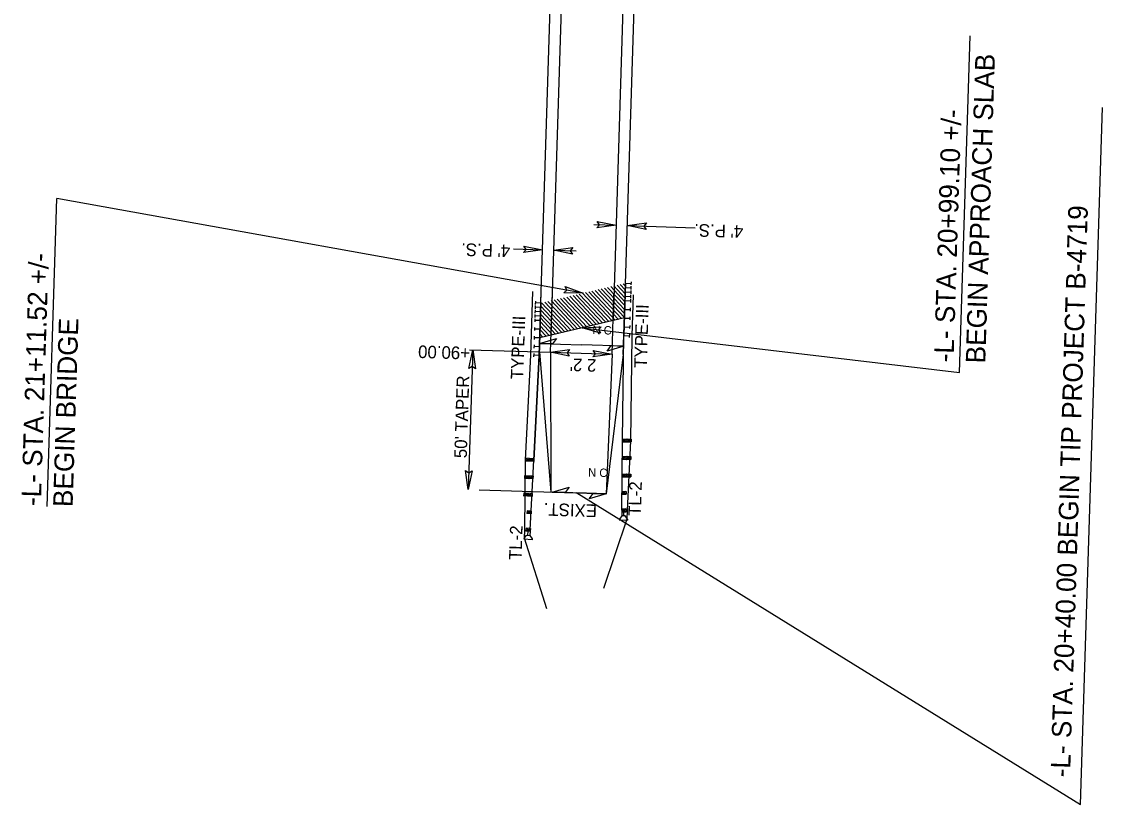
# Model space of a CAD drawing. Extents: x 1515198 to 1515601, y 565062 to 565830.
# Drawn here: x 1515197.9 to 1515584.6, y 565062 to 565342 of the extents above; entities that cross this region are included whole.
import ezdxf

# ---------------------------------------------------------------- set-up
doc = ezdxf.new("R2010")
doc.units = 0
for name, color, linetype in [('Old_Level_1', 7, 'Continuous'), ('Old_Level_3', 7, 'Continuous'), ('Prop Approach Slab', 7, 'Continuous'), ('Prop Approach Slab Hatching', 7, 'Continuous'), ('Prop Dimension', 7, 'Continuous'), ('Prop Dimension Text', 7, 'Continuous'), ('Prop EOT', 7, 'Continuous'), ('Prop Guardrail', 7, 'Continuous'), ('Prop Guardrail Anchor Unit CELL', 7, 'Continuous'), ('Prop Horizontal Alignment Curve and Spiral Data', 7, 'Continuous'), ('Prop Horizontal Alignment Tick Small', 7, 'Continuous'), ('Prop Lane Lines', 7, 'Continuous'), ('Prop Paved Shoulder', 7, 'Continuous'), ('Prop Roadway Bridge', 7, 'Continuous'), ('Prop Structure Anchor Unit CELL', 7, 'Continuous'), ('Prop Superelevation  Arrow CELL', 7, 'Continuous'), ('Prop Superelevation Label', 7, 'Continuous'), ('Prop Terminator CELL', 7, 'Continuous')]:
    doc.layers.add(name, color=color, linetype=linetype)

msp = doc.modelspace()

# ---------------------------------------------------------------- linework, layer by layer
at = {"layer": 'Old_Level_1'}
for p, q in [((1515380.08, 565222.69), (1515380.79, 565245.45)), ((1515416.32, 565229.6), (1515416.78, 565244.32)), ((1515415.89, 565192.09), (1515416.32, 565229.6)), ((1515378.16, 565185.23), (1515380.08, 565222.69)), ((1515414.61, 565167.12), (1515415.89, 565192.09)), ((1515377.87, 565160.23), (1515378.16, 565185.23)), ((1515414.51, 565164.12), (1515414.61, 565167.12)), ((1515406.23, 565139.37), (1515414.51, 565164.12)), ((1515377.78, 565157.23), (1515377.87, 565160.23)), ((1515385.82, 565131.97), (1515377.78, 565157.23))]:
    msp.add_line(p, q, dxfattribs=at)
at = {"layer": 'Old_Level_3'}
for p, q in [((1515383.07, 565222.6), (1515383.78, 565245.36)), ((1515413.33, 565229.69), (1515413.79, 565244.41)), ((1515412.9, 565192.19), (1515413.33, 565229.69)), ((1515413.33, 565229.69), (1515413.33, 565229.69)), ((1515381.15, 565185.14), (1515383.07, 565222.6)), ((1515383.07, 565222.6), (1515383.07, 565222.6)), ((1515412.62, 565167.19), (1515412.9, 565192.19)), ((1515379.86, 565160.17), (1515381.15, 565185.14))]:
    msp.add_line(p, q, dxfattribs=at)
at = {"layer": 'Prop Approach Slab'}
for p, q in [((1515413.52, 565236.02), (1515413.9, 565248.43)), ((1515383.28, 565228.92), (1515383.67, 565241.34)), ((1515413.52, 565236.02), (1515383.28, 565228.92))]:
    msp.add_line(p, q, dxfattribs=at)
at = {"layer": 'Prop Approach Slab Hatching'}
for p, q in [((1515413.79, 565244.64), (1515410.89, 565247.72)), ((1515413.83, 565246.06), (1515412.01, 565247.99)), ((1515413.87, 565247.47), (1515413.14, 565248.25)), ((1515403.51, 565233.67), (1515394.03, 565243.77)), ((1515404.64, 565233.93), (1515395.15, 565244.03)), ((1515405.76, 565234.2), (1515396.28, 565244.3)), ((1515406.89, 565234.46), (1515397.4, 565244.56)), ((1515408.01, 565234.72), (1515398.52, 565244.82)), ((1515409.13, 565234.99), (1515399.65, 565245.09)), ((1515410.26, 565235.25), (1515400.77, 565245.35)), ((1515411.38, 565235.51), (1515401.9, 565245.61)), ((1515412.51, 565235.78), (1515403.02, 565245.88)), ((1515413.52, 565236.16), (1515404.14, 565246.14)), ((1515413.56, 565237.57), (1515405.27, 565246.41)), ((1515413.61, 565238.99), (1515406.39, 565246.67)), ((1515413.65, 565240.4), (1515407.52, 565246.93)), ((1515413.7, 565241.81), (1515408.64, 565247.2)), ((1515413.74, 565243.23), (1515409.77, 565247.46)), ((1515392.27, 565231.03), (1515383.63, 565240.23)), ((1515393.4, 565231.29), (1515383.91, 565241.39)), ((1515394.52, 565231.56), (1515385.03, 565241.66)), ((1515395.64, 565231.82), (1515386.16, 565241.92)), ((1515396.77, 565232.09), (1515387.28, 565242.19)), ((1515397.89, 565232.35), (1515388.41, 565242.45)), ((1515399.02, 565232.61), (1515389.53, 565242.71)), ((1515400.14, 565232.88), (1515390.65, 565242.98)), ((1515401.27, 565233.14), (1515391.78, 565243.24)), ((1515402.39, 565233.4), (1515392.9, 565243.5)), ((1515390.02, 565230.5), (1515383.54, 565237.4)), ((1515391.15, 565230.77), (1515383.59, 565238.82)), ((1515386.65, 565229.71), (1515383.41, 565233.16)), ((1515387.78, 565229.98), (1515383.46, 565234.57)), ((1515388.9, 565230.24), (1515383.5, 565235.99)), ((1515384.4, 565229.18), (1515383.32, 565230.33)), ((1515385.53, 565229.45), (1515383.37, 565231.75))]:
    msp.add_line(p, q, dxfattribs=at)
at = {"layer": 'Prop Dimension'}
for p, q in [((1515402.56, 565269.42), (1515410.55, 565269.17)), ((1515414.57, 565269.05), (1515438.83, 565268.29)), ((1515373.86, 565260.68), (1515384.26, 565260.36)), ((1515388.26, 565260.23), (1515396.26, 565259.98)), ((1515359.26, 565224.59), (1515357.69, 565174.62)), ((1515358.13, 565224.63), (1515387.12, 565223.72)), ((1515387.12, 565223.72), (1515398.11, 565223.37)), ((1515398.11, 565223.37), (1515409.11, 565223.03)), ((1515361.56, 565174.5), (1515403.95, 565173.17))]:
    msp.add_line(p, q, dxfattribs=at)
at = {"layer": 'Prop EOT'}
for p, q in [((1515387.12, 565223.72), (1515387.79, 565245.23)), ((1515409.11, 565223.03), (1515409.78, 565244.54)), ((1515387.12, 565223.72), (1515387.23, 565173.69)), ((1515409.11, 565223.03), (1515407.02, 565173.07)), ((1515407.02, 565173.07), (1515387.23, 565173.69))]:
    msp.add_line(p, q, dxfattribs=at)
at = {"layer": 'Prop Guardrail'}
for p, q in [((1515412.89, 565192.19), (1515413.32, 565229.69)), ((1515413.32, 565229.69), (1515413.32, 565229.69)), ((1515383.08, 565222.6), (1515381.16, 565185.14)), ((1515381.16, 565185.14), (1515381.16, 565185.14))]:
    msp.add_line(p, q, dxfattribs=at)
at = {"layer": 'Prop Guardrail Anchor Unit CELL'}
for p, q in [((1515412.61, 565167.19), (1515412.89, 565192.19)), ((1515412.9, 565192.69), (1515412.89, 565191.69)), ((1515414.42, 565192.67), (1515412.89, 565191.69)), ((1515412.89, 565191.69), (1515415.92, 565191.65)), ((1515412.9, 565192.69), (1515415.93, 565192.65)), ((1515412.9, 565192.69), (1515414.4, 565191.67)), ((1515414.42, 565192.67), (1515414.4, 565191.67)), ((1515414.4, 565191.67), (1515415.93, 565192.65)), ((1515415.92, 565191.65), (1515414.42, 565192.67)), ((1515415.93, 565192.65), (1515415.92, 565191.65)), ((1515378.15, 565185.79), (1515378.1, 565184.8)), ((1515381.18, 565185.64), (1515378.15, 565185.79)), ((1515379.61, 565184.72), (1515378.15, 565185.79)), ((1515412.83, 565186.44), (1515412.82, 565185.44)), ((1515414.35, 565186.42), (1515412.82, 565185.44)), ((1515412.83, 565186.44), (1515415.86, 565186.4)), ((1515412.83, 565186.44), (1515414.33, 565185.42)), ((1515414.35, 565186.42), (1515414.33, 565185.42)), ((1515414.33, 565185.42), (1515415.86, 565186.4)), ((1515415.85, 565185.4), (1515414.35, 565186.42)), ((1515415.86, 565186.4), (1515415.85, 565185.4)), ((1515378.1, 565184.8), (1515379.67, 565185.72)), ((1515381.13, 565184.64), (1515378.1, 565184.8)), ((1515379.67, 565185.72), (1515379.61, 565184.72)), ((1515381.18, 565185.64), (1515379.61, 565184.72)), ((1515379.67, 565185.72), (1515381.13, 565184.64)), ((1515379.87, 565160.17), (1515381.16, 565185.14)), ((1515381.18, 565185.64), (1515381.13, 565184.64)), ((1515412.82, 565185.44), (1515415.85, 565185.4)), ((1515377.83, 565179.55), (1515377.78, 565178.55)), ((1515377.78, 565178.55), (1515379.34, 565179.47)), ((1515380.81, 565178.4), (1515377.78, 565178.55)), ((1515380.86, 565179.4), (1515377.83, 565179.55)), ((1515379.29, 565178.48), (1515377.83, 565179.55)), ((1515379.34, 565179.47), (1515379.29, 565178.48)), ((1515380.86, 565179.4), (1515379.29, 565178.48)), ((1515379.34, 565179.47), (1515380.81, 565178.4)), ((1515380.86, 565179.4), (1515380.81, 565178.4)), ((1515412.76, 565180.19), (1515412.74, 565179.19)), ((1515414.27, 565180.17), (1515412.74, 565179.19)), ((1515412.74, 565179.19), (1515415.78, 565179.15)), ((1515412.76, 565180.19), (1515415.79, 565180.15)), ((1515412.76, 565180.19), (1515414.26, 565179.17)), ((1515414.27, 565180.17), (1515414.26, 565179.17)), ((1515414.26, 565179.17), (1515415.79, 565180.15)), ((1515415.78, 565179.15), (1515414.27, 565180.17)), ((1515415.79, 565180.15), (1515415.78, 565179.15)), ((1515377.51, 565173.31), (1515377.46, 565172.31)), ((1515377.46, 565172.31), (1515379.02, 565173.23)), ((1515380.49, 565172.16), (1515377.46, 565172.31)), ((1515380.54, 565173.15), (1515377.51, 565173.31)), ((1515378.97, 565172.23), (1515377.51, 565173.31)), ((1515379.02, 565173.23), (1515378.97, 565172.23)), ((1515380.54, 565173.15), (1515378.97, 565172.23)), ((1515379.02, 565173.23), (1515380.49, 565172.16)), ((1515380.54, 565173.15), (1515380.49, 565172.16)), ((1515412.69, 565173.94), (1515412.67, 565172.94)), ((1515414.2, 565173.92), (1515412.67, 565172.94)), ((1515412.67, 565172.94), (1515414.19, 565172.92)), ((1515412.69, 565173.94), (1515414.2, 565173.92)), ((1515412.69, 565173.94), (1515414.19, 565172.92)), ((1515414.2, 565173.92), (1515414.19, 565172.92)), ((1515378.7, 565166.99), (1515378.65, 565165.99)), ((1515380.22, 565166.91), (1515378.65, 565165.99)), ((1515380.22, 565166.91), (1515378.7, 565166.99)), ((1515378.7, 565166.99), (1515380.17, 565165.91)), ((1515380.22, 565166.91), (1515380.17, 565165.91)), ((1515412.61, 565167.69), (1515412.6, 565166.69)), ((1515414.13, 565167.67), (1515412.6, 565166.69)), ((1515412.61, 565166.69), (1515412.6, 565165.22)), ((1515412.6, 565166.69), (1515414.12, 565166.67)), ((1515412.61, 565167.69), (1515414.13, 565167.67)), ((1515412.61, 565167.69), (1515414.12, 565166.67)), ((1515413.32, 565165.21), (1515413.33, 565166.68)), ((1515414.13, 565167.67), (1515414.12, 565166.67)), ((1515380.17, 565165.91), (1515378.65, 565165.99)), ((1515411.73, 565164.05), (1515411.72, 565163.74)), ((1515411.72, 565163.74), (1515414.66, 565163.71)), ((1515412.6, 565165.22), (1515411.73, 565164.05)), ((1515413.82, 565165.2), (1515412.6, 565165.22)), ((1515414.67, 565164.02), (1515413.82, 565165.2)), ((1515414.67, 565164.02), (1515414.66, 565163.71)), ((1515378.38, 565160.75), (1515378.33, 565159.75)), ((1515379.9, 565160.67), (1515378.33, 565159.75)), ((1515379.85, 565159.67), (1515378.33, 565159.75)), ((1515379.9, 565160.67), (1515378.38, 565160.75)), ((1515378.38, 565160.75), (1515379.85, 565159.67)), ((1515379.04, 565158.24), (1515379.12, 565159.71)), ((1515379.84, 565159.67), (1515379.76, 565158.2)), ((1515379.9, 565160.67), (1515379.85, 565159.67)), ((1515377.62, 565157.14), (1515377.6, 565156.83)), ((1515380.54, 565156.68), (1515377.6, 565156.83)), ((1515377.62, 565157.14), (1515378.54, 565158.27)), ((1515378.54, 565158.27), (1515379.76, 565158.21)), ((1515379.76, 565158.2), (1515380.56, 565156.98)), ((1515380.56, 565156.98), (1515380.54, 565156.68))]:
    msp.add_line(p, q, dxfattribs=at)
at = {"layer": 'Prop Horizontal Alignment Tick Small'}
for p, q in [((1515533.48, 565216.47), (1515537.26, 565336.99)), ((1515576.74, 565061.98), (1515584.56, 565311.28)), ((1515207.05, 565168.56), (1515210.5, 565278.77)), ((1515398.79, 565244.88), (1515210.5, 565278.77)), ((1515398.4, 565232.47), (1515533.48, 565216.47)), ((1515396.55, 565173.4), (1515576.74, 565061.98))]:
    msp.add_line(p, q, dxfattribs=at)
at = {"layer": 'Prop Lane Lines'}
for p, q in [((1515387.31, 565229.87), (1515393.95, 565441.61)), ((1515415.94, 565440.92), (1515409.48, 565235.07))]:
    msp.add_line(p, q, dxfattribs=at)
at = {"layer": 'Prop Paved Shoulder'}
for p, q in [((1515383.12, 565223.84), (1515383.79, 565245.35)), ((1515413.1, 565222.9), (1515413.78, 565244.42)), ((1515383.12, 565223.84), (1515387.23, 565173.69)), ((1515413.1, 565222.9), (1515407.02, 565173.07))]:
    msp.add_line(p, q, dxfattribs=at)
at = {"layer": 'Prop Roadway Bridge'}
for p, q in [((1515383.79, 565245.35), (1515388.95, 565410)), ((1515413.78, 565244.42), (1515418.94, 565409.06))]:
    msp.add_line(p, q, dxfattribs=at)
at = {"layer": 'Prop Structure Anchor Unit CELL'}
for p, q in [((1515413.9, 565248.43), (1515413.32, 565229.69)), ((1515413.9, 565248.43), (1515415.9, 565248.37)), ((1515415.92, 565248.94), (1515415.89, 565247.8)), ((1515413.76, 565243.75), (1515415.76, 565243.68)), ((1515413.81, 565245.31), (1515415.81, 565245.25)), ((1515413.86, 565246.87), (1515415.85, 565246.81)), ((1515415.77, 565244.26), (1515415.74, 565243.11)), ((1515415.82, 565245.82), (1515415.79, 565244.67)), ((1515415.87, 565247.38), (1515415.84, 565246.24)), ((1515381.64, 565240.41), (1515381.6, 565239.27)), ((1515381.69, 565241.97), (1515381.65, 565240.83)), ((1515383.67, 565241.34), (1515381.67, 565241.4)), ((1515383.67, 565241.34), (1515383.08, 565222.6)), ((1515413.71, 565242.19), (1515415.71, 565242.12)), ((1515415.73, 565242.7), (1515415.69, 565241.55)), ((1515381.54, 565237.29), (1515381.5, 565236.14)), ((1515383.52, 565236.65), (1515381.52, 565236.72)), ((1515381.59, 565238.85), (1515381.55, 565237.7)), ((1515383.57, 565238.21), (1515381.57, 565238.28)), ((1515383.62, 565239.78), (1515381.62, 565239.84)), ((1515413.61, 565239.06), (1515415.61, 565239)), ((1515415.53, 565236.45), (1515415.49, 565235.3)), ((1515415.63, 565239.57), (1515415.59, 565238.43)), ((1515381.39, 565232.6), (1515381.36, 565231.46)), ((1515381.49, 565235.73), (1515381.45, 565234.58)), ((1515383.47, 565235.09), (1515381.47, 565235.15)), ((1515413.42, 565232.82), (1515415.41, 565232.75)), ((1515413.51, 565235.94), (1515415.51, 565235.88)), ((1515415.43, 565233.32), (1515415.4, 565232.18)), ((1515381.29, 565229.48), (1515381.26, 565228.33)), ((1515383.28, 565228.84), (1515381.28, 565228.91)), ((1515383.37, 565231.97), (1515381.37, 565232.03)), ((1515413.32, 565229.69), (1515415.32, 565229.63)), ((1515415.33, 565230.2), (1515415.3, 565229.06)), ((1515381.2, 565226.36), (1515381.16, 565225.21)), ((1515383.18, 565225.72), (1515381.18, 565225.78)), ((1515381.1, 565223.23), (1515381.06, 565222.09)), ((1515383.08, 565222.6), (1515381.08, 565222.66))]:
    msp.add_line(p, q, dxfattribs=at)
at = {"layer": 'Prop Superelevation  Arrow CELL'}
for p, q in [((1515383.21, 565226.89), (1515398.21, 565226.42)), ((1515413.39, 565225.94), (1515398.21, 565226.42)), ((1515387.73, 565173.68), (1515396.55, 565173.4)), ((1515407.02, 565173.07), (1515396.55, 565173.4))]:
    msp.add_line(p, q, dxfattribs=at)
for points in [[(1515383.21, 565226.89), (1515389.27, 565228.7), (1515387.84, 565226.74)], [(1515413.39, 565225.94), (1515407.33, 565224.13), (1515408.76, 565226.09)], [(1515387.73, 565173.68), (1515393.79, 565175.49), (1515392.35, 565173.53)], [(1515407.02, 565173.07), (1515400.96, 565171.26), (1515402.39, 565173.22)]]:
    msp.add_lwpolyline(points, close=True, dxfattribs=at)
at = {"layer": 'Prop Terminator CELL'}
for points in [[(1515403.84, 565270.55), (1515410.55, 565269.17), (1515403.73, 565268.19), (1515404.63, 565269.36)], [(1515421.28, 565267.67), (1515414.57, 565269.05), (1515421.4, 565270.03), (1515420.5, 565268.86)], [(1515377.55, 565261.73), (1515384.26, 565260.36), (1515377.44, 565259.37), (1515378.34, 565260.54)], [(1515394.97, 565258.86), (1515388.26, 565260.23), (1515395.08, 565261.22), (1515394.18, 565260.05)], [(1515392.37, 565247.28), (1515398.79, 565244.88), (1515391.89, 565244.96), (1515392.96, 565245.98)], [(1515404.96, 565230.52), (1515398.4, 565232.47), (1515405.28, 565232.86), (1515404.28, 565231.77)], [(1515357.88, 565217.88), (1515359.26, 565224.59), (1515360.24, 565217.77), (1515359.07, 565218.67)], [(1515393.83, 565222.35), (1515387.12, 565223.72), (1515393.94, 565224.71), (1515393.04, 565223.53)], [(1515402.4, 565224.4), (1515409.11, 565223.03), (1515402.28, 565222.04), (1515403.18, 565223.22)], [(1515359.06, 565181.33), (1515357.69, 565174.62), (1515356.7, 565181.44), (1515357.88, 565180.54)]]:
    msp.add_lwpolyline(points, close=True, dxfattribs=at)

# ---------------------------------------------------------------- texts
at = {"layer": 'Prop Dimension Text'}
for s, rotation, p in [("4' P.S.", 178.205, (1515456.1, 565269.11)), ("4' P.S.", 178.205, (1515372.73, 565262.2)), ('TYPE-III', 88.205, (1515421.52, 565218.11)), ('TYPE-III', 88.205, (1515377.36, 565214.01)), ('+90.00', 178.205, (1515358.37, 565225.63)), ("2 2'", 178.205, (1515403.59, 565221.23)), ("50' TAPER", 88.205, (1515357.14, 565185.78)), ('TL-2', 88.205, (1515419.42, 565165.11)), ('EXIST.', 178.205, (1515403.81, 565169.22)), ('TL-2', 88.205, (1515376.74, 565149.33))]:
    msp.add_text(s, height=4.5, rotation=rotation, dxfattribs=at).set_placement(p)
at = {"layer": 'Prop Horizontal Alignment Curve and Spiral Data'}
for s, p in [('BEGIN APPROACH SLAB', (1515542.65, 565219.68)), ('-L- STA. 20+99.10 +/-', (1515531.28, 565220.04)), ('-L- STA. 20+40.00 BEGIN TIP PROJECT B-4719', (1515572.98, 565071.58)), ('-L- STA. 21+11.52 +/-', (1515204.74, 565168.64)), ('BEGIN BRIDGE', (1515216.11, 565168.28))]:
    msp.add_text(s, height=7, rotation=88.205, dxfattribs=at).set_placement(p)
at = {"layer": 'Prop Superelevation Label'}
for p in [(1515402.07, 565230.26), (1515400.51, 565179.29)]:
    msp.add_text('N C', height=3, rotation=358.205, dxfattribs=at).set_placement(p)

doc.saveas('drawing.dxf')
